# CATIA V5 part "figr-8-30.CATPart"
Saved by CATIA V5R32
Part number: Part1
Bounding box of the stored display mesh (mm): x -50 to 50, y -75 to 125, z 0 to 40
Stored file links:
  D:\PROJECTS\Project 2022\CATIA V5 6R 2022\Resources\Part Files\c08_catia_v5_6r2022_prt\figr-8-30.CATPart
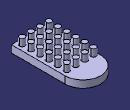
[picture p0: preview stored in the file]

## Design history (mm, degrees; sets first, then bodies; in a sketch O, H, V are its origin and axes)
Body1 (main body)
  Sketch1 on xy-plane, origin (0, 0, 0), H (1, 0, 0), V (0, 1, 0)
    line L1 (50, 75) -> (50, -75)
    line L2 (50, -75) -> (-50, -75)
    line L3 (-50, -75) -> (-50, 75)
    arc A1 centre (0, 75) radius 50 from (-50, 75) to (50, 75) cw
    point P5 (0, 75)
    axis line L4 (50, -75) -> (-50, 75)
    length L2 = 100
    distance P5 L2 = 150
    horizontal: L2 H
    vertical: L1 V, L3 V
    tangency: A1 L3, A1 L1
    midpoint: O L4
  Pad1: profile Sketch1, direction (0, 0, 1), length 20
  Sketch2 on face of Pad1, origin (0, 0, 20), H (1, 0, 0), V (0, 1, 0)
    circle A1 centre (35, -60) radius 7.5
    point P1 (35, -60)
    reference projected line E1 (-50, -75) -> (50, -75) from edge [face of Pad1 | face of Pad1]
    reference projected line E2 (50, -75) -> (50, 75) from edge [face of Pad1 | face of Pad1]
    distance P1 E1 = 15
    distance P1 E2 = 15
    radius A1 = 7.5
  Pad2: profile Sketch2, direction (0, 0, 1), length 20
  RectPattern1: of Pad2, direction 1 instances 4, spacing 25, along edge [face of Pad1 | face of Pad1] reversed, direction 2 instances 6, spacing 25, along edge [face of Pad1 | face of Pad1]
